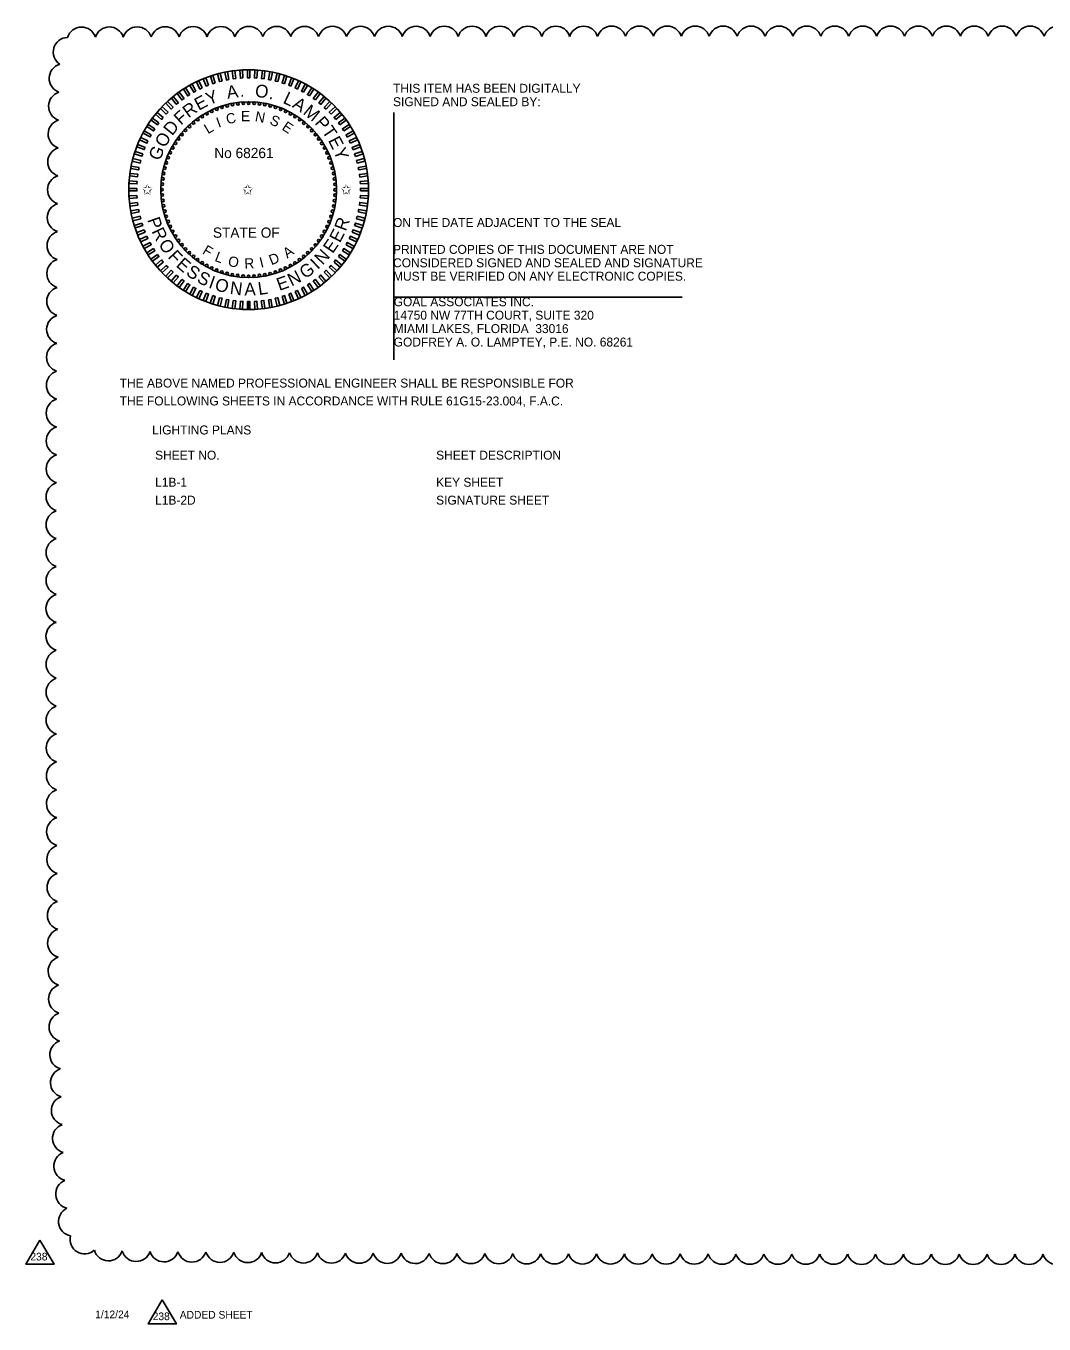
# Model space of a CAD drawing. Extents: x -811.2 to -795, y -2295.2 to -2235.1.
# Drawn here: x -811.23 to -803.27, y -2294.97 to -2284.82 of the extents above; entities that cross this region are included whole.
import ezdxf

# ---------------------------------------------------------------- set-up
doc = ezdxf.new("R2010")
doc.units = 0
for name, color, linetype in [('AdhocPoint_dp', 7, 'Continuous'), ('Cloud_dp', 7, 'Continuous'), ('PlotBorder_dp', 7, 'Continuous'), ('TextMinor', 7, 'Continuous'), ('TextMisc', 7, 'Continuous'), ('TextShtNo', 7, 'Continuous')]:
    doc.layers.add(name, color=color, linetype=linetype)

msp = doc.modelspace()

# ---------------------------------------------------------------- linework, layer by layer
at = {"layer": 'AdhocPoint_dp'}
for p, q in [((-808.355, -2285.496), (-808.355, -2287.431)), ((-808.355, -2286.941), (-806.098, -2286.941))]:
    msp.add_line(p, q, dxfattribs=at)
at = {"layer": 'Cloud_dp'}
for points in [[(-811.125, -2294.318), (-811.233, -2294.506), (-811.012, -2294.506)], [(-810.168, -2294.785), (-810.276, -2294.973), (-810.055, -2294.973)]]:
    msp.add_lwpolyline(points, close=True, dxfattribs=at)
for centre, start, end in [((-810.798, -2284.941), 18.0566, 163.0566), ((-810.58, -2284.94), 17.7998, 162.7998), ((-810.362, -2284.939), 17.7187, 162.7187), ((-810.143, -2284.938), 17.6743, 162.6743), ((-809.925, -2284.937), 17.6451, 162.6451), ((-809.707, -2284.937), 17.624, 162.624), ((-809.488, -2284.936), 17.6079, 162.6079), ((-809.27, -2284.936), 17.5951, 162.5951), ((-809.052, -2284.936), 17.5845, 162.5845), ((-808.834, -2284.935), 17.5756, 162.5756), ((-808.615, -2284.935), 17.568, 162.568), ((-808.397, -2284.935), 17.5614, 162.5614), ((-808.179, -2284.935), 17.5556, 162.5556), ((-807.96, -2284.934), 17.5505, 162.5505), ((-807.742, -2284.934), 17.5459, 162.5459), ((-807.524, -2284.934), 17.5417, 162.5417), ((-807.305, -2284.934), 17.5379, 162.5379), ((-807.087, -2284.934), 17.5344, 162.5344), ((-806.869, -2284.934), 17.5313, 162.5313), ((-806.65, -2284.933), 17.5283, 162.5283), ((-806.432, -2284.933), 17.5256, 162.5256), ((-806.214, -2284.933), 17.5231, 162.5231), ((-805.995, -2284.933), 17.5207, 162.5207), ((-805.777, -2284.933), 17.5185, 162.5185), ((-805.559, -2284.933), 17.5164, 162.5164), ((-805.34, -2284.933), 17.5145, 162.5145), ((-805.122, -2284.933), 17.5126, 162.5126), ((-804.904, -2284.933), 17.5109, 162.5109), ((-804.685, -2284.933), 17.5092, 162.5092), ((-804.467, -2284.933), 17.5077, 162.5077), ((-804.249, -2284.933), 17.5062, 162.5062), ((-804.03, -2284.933), 17.5048, 162.5048), ((-803.812, -2284.933), 17.5034, 162.5034), ((-803.594, -2284.933), 17.5021, 162.5021), ((-803.375, -2284.933), 17.5009, 162.5009), ((-803.157, -2284.933), 17.5, 162.5), ((-810.905, -2285.022), 91.4771, 236.4771), ((-810.937, -2285.228), 105.908, 250.908), ((-810.942, -2285.446), 106.4168, 251.4168), ((-810.945, -2285.664), 106.6762, 251.6762), ((-810.948, -2285.882), 106.841, 251.841), ((-810.95, -2286.1), 106.9576, 251.9576), ((-810.952, -2286.318), 107.0457, 252.0457), ((-810.954, -2286.537), 107.1154, 252.1154), ((-810.955, -2286.755), 107.1722, 252.1722), ((-810.956, -2286.973), 107.2198, 252.2198), ((-810.957, -2287.192), 107.2603, 252.2603), ((-810.958, -2287.41), 107.2954, 252.2954), ((-810.959, -2287.628), 107.3262, 252.3262), ((-810.96, -2287.847), 107.3535, 252.3535), ((-810.96, -2288.065), 107.3779, 252.3779), ((-810.96, -2288.283), 107.3998, 252.3998), ((-810.961, -2288.501), 107.4198, 252.4198), ((-810.961, -2288.72), 107.438, 252.438), ((-810.961, -2288.938), 107.4547, 252.4547), ((-810.961, -2289.156), 107.4701, 252.4701), ((-810.962, -2289.375), 107.4843, 252.4843), ((-810.962, -2289.593), 107.499, 252.499), ((-810.961, -2289.811), 107.5356, 252.5356), ((-810.961, -2290.03), 107.5822, 252.5822), ((-810.961, -2290.248), 107.6325, 252.6325), ((-810.96, -2290.466), 107.6869, 252.6869), ((-810.959, -2290.685), 107.7461, 252.7461), ((-810.958, -2290.903), 107.8108, 252.8108), ((-810.957, -2291.121), 107.8818, 252.8818), ((-810.955, -2291.339), 107.9604, 252.9604), ((-810.954, -2291.558), 108.0479, 253.0479), ((-810.951, -2291.776), 108.1461, 253.1461), ((-810.949, -2291.994), 108.2576, 253.2576), ((-810.945, -2292.212), 108.3854, 253.3854), ((-810.942, -2292.431), 108.534, 253.534), ((-810.938, -2292.649), 108.7099, 253.7099), ((-810.932, -2292.867), 108.9225, 253.9225), ((-810.927, -2293.085), 109.1867, 254.1867), ((-810.92, -2293.303), 109.5275, 254.5275), ((-810.911, -2293.521), 109.9909, 254.9909), ((-810.9, -2293.738), 110.6749, 255.6749), ((-810.886, -2293.956), 111.8417, 256.8417), ((-810.864, -2294.171), 114.6718, 259.6718), ((-810.774, -2294.311), 166.2299, 311.2299), ((-810.588, -2294.365), 196.1072, 341.1072), ((-810.37, -2294.37), 196.5738, 341.5738), ((-810.152, -2294.373), 196.7877, 341.7877), ((-809.934, -2294.375), 196.9179, 341.9179), ((-809.715, -2294.377), 197.008, 342.008), ((-809.497, -2294.379), 197.075, 342.075), ((-809.279, -2294.381), 197.1274, 342.1274), ((-809.061, -2294.382), 197.1699, 342.1699), ((-808.842, -2294.383), 197.2052, 342.2052), ((-808.624, -2294.384), 197.2352, 342.2352), ((-808.406, -2294.385), 197.261, 342.261), ((-808.187, -2294.386), 197.2836, 342.2836), ((-807.969, -2294.387), 197.3036, 342.3036), ((-807.751, -2294.387), 197.3214, 342.3214), ((-807.532, -2294.388), 197.3374, 342.3374), ((-807.314, -2294.389), 197.3519, 342.3519), ((-807.096, -2294.389), 197.3651, 342.3651), ((-806.878, -2294.39), 197.3773, 342.3773), ((-806.659, -2294.39), 197.3884, 342.3884), ((-806.441, -2294.391), 197.3987, 342.3987), ((-806.223, -2294.391), 197.4083, 342.4083), ((-806.004, -2294.391), 197.4172, 342.4172), ((-805.786, -2294.392), 197.4256, 342.4256), ((-805.568, -2294.392), 197.4334, 342.4334), ((-805.349, -2294.392), 197.4407, 342.4407), ((-805.131, -2294.392), 197.4476, 342.4476), ((-804.913, -2294.392), 197.4542, 342.4542), ((-804.694, -2294.393), 197.4604, 342.4604), ((-804.476, -2294.393), 197.4662, 342.4662), ((-804.258, -2294.393), 197.4718, 342.4718), ((-804.039, -2294.393), 197.4771, 342.4771), ((-803.821, -2294.393), 197.4821, 342.4821), ((-803.603, -2294.393), 197.487, 342.487), ((-803.384, -2294.393), 197.4916, 342.4916), ((-803.166, -2294.393), 197.496, 342.496)]:
    msp.add_arc(centre, 0.114, start, end, dxfattribs=at)
at = {"layer": 'TextMinor'}
for radius in [0.938, 0.688]:
    msp.add_circle((-809.49, -2286.099), radius, dxfattribs=at)
at = {"layer": 'TextShtNo'}
for p, q in [((-809.5, -2287.037), (-809.5, -2286.974)), ((-809.49, -2287.037), (-809.49, -2286.974)), ((-809.48, -2287.037), (-809.48, -2286.974))]:
    msp.add_line(p, q, dxfattribs=at)
for points in [[(-809.698, -2285.249), (-809.717, -2285.254), (-809.733, -2285.194), (-809.713, -2285.189)], [(-809.644, -2285.238), (-809.664, -2285.242), (-809.676, -2285.18), (-809.656, -2285.176)], [(-809.59, -2285.23), (-809.61, -2285.232), (-809.618, -2285.17), (-809.598, -2285.168)], [(-809.535, -2285.225), (-809.555, -2285.227), (-809.559, -2285.164), (-809.539, -2285.163)], [(-809.48, -2285.224), (-809.5, -2285.224), (-809.5, -2285.162), (-809.48, -2285.162)], [(-809.425, -2285.227), (-809.445, -2285.225), (-809.441, -2285.163), (-809.421, -2285.164)], [(-809.37, -2285.232), (-809.39, -2285.23), (-809.383, -2285.168), (-809.363, -2285.17)], [(-809.316, -2285.242), (-809.336, -2285.238), (-809.324, -2285.177), (-809.304, -2285.18)], [(-809.263, -2285.254), (-809.282, -2285.249), (-809.267, -2285.189), (-809.247, -2285.194)], [(-809.95, -2285.355), (-809.967, -2285.366), (-810.001, -2285.313), (-809.984, -2285.302)], [(-809.903, -2285.328), (-809.92, -2285.337), (-809.951, -2285.283), (-809.933, -2285.273)], [(-809.853, -2285.303), (-809.872, -2285.312), (-809.898, -2285.255), (-809.88, -2285.247)], [(-809.803, -2285.282), (-809.822, -2285.289), (-809.845, -2285.231), (-809.826, -2285.224)], [(-809.751, -2285.264), (-809.77, -2285.27), (-809.789, -2285.211), (-809.77, -2285.205)], [(-809.21, -2285.27), (-809.229, -2285.264), (-809.21, -2285.205), (-809.191, -2285.211)], [(-809.159, -2285.289), (-809.177, -2285.282), (-809.154, -2285.224), (-809.136, -2285.231)], [(-809.108, -2285.312), (-809.127, -2285.303), (-809.1, -2285.247), (-809.082, -2285.255)], [(-809.06, -2285.337), (-809.077, -2285.328), (-809.047, -2285.273), (-809.03, -2285.283)], [(-809.013, -2285.366), (-809.03, -2285.355), (-808.996, -2285.302), (-808.979, -2285.313)], [(-810.04, -2285.419), (-810.056, -2285.431), (-810.095, -2285.383), (-810.08, -2285.37)], [(-809.996, -2285.385), (-810.013, -2285.397), (-810.049, -2285.347), (-810.033, -2285.335)], [(-808.968, -2285.397), (-808.984, -2285.385), (-808.947, -2285.335), (-808.931, -2285.347)], [(-808.925, -2285.432), (-808.94, -2285.419), (-808.9, -2285.371), (-808.885, -2285.383)], [(-810.158, -2285.534), (-810.171, -2285.549), (-810.219, -2285.509), (-810.206, -2285.494)], [(-810.121, -2285.493), (-810.135, -2285.508), (-810.18, -2285.465), (-810.167, -2285.45)], [(-810.082, -2285.454), (-810.096, -2285.468), (-810.139, -2285.423), (-810.124, -2285.409)], [(-808.884, -2285.468), (-808.898, -2285.455), (-808.856, -2285.409), (-808.841, -2285.423)], [(-808.845, -2285.508), (-808.859, -2285.493), (-808.814, -2285.45), (-808.8, -2285.465)], [(-808.809, -2285.549), (-808.822, -2285.534), (-808.774, -2285.494), (-808.761, -2285.51)], [(-810.223, -2285.622), (-810.234, -2285.639), (-810.287, -2285.605), (-810.276, -2285.588)], [(-810.192, -2285.577), (-810.204, -2285.593), (-810.254, -2285.556), (-810.243, -2285.54)], [(-808.776, -2285.593), (-808.788, -2285.577), (-808.738, -2285.54), (-808.726, -2285.556)], [(-808.746, -2285.639), (-808.757, -2285.622), (-808.704, -2285.588), (-808.693, -2285.606)], [(-810.278, -2285.717), (-810.286, -2285.736), (-810.343, -2285.709), (-810.334, -2285.691)], [(-810.252, -2285.669), (-810.262, -2285.686), (-810.316, -2285.656), (-810.307, -2285.639)], [(-808.718, -2285.687), (-808.728, -2285.669), (-808.673, -2285.639), (-808.664, -2285.657)], [(-808.694, -2285.736), (-808.703, -2285.718), (-808.646, -2285.691), (-808.638, -2285.709)], [(-810.319, -2285.819), (-810.325, -2285.838), (-810.385, -2285.819), (-810.379, -2285.8)], [(-810.3, -2285.768), (-810.307, -2285.786), (-810.365, -2285.763), (-810.358, -2285.745)], [(-808.673, -2285.787), (-808.68, -2285.768), (-808.622, -2285.745), (-808.615, -2285.764)], [(-808.655, -2285.839), (-808.661, -2285.819), (-808.602, -2285.8), (-808.595, -2285.819)], [(-810.335, -2285.872), (-810.34, -2285.891), (-810.401, -2285.876), (-810.396, -2285.856)], [(-808.64, -2285.892), (-808.645, -2285.872), (-808.585, -2285.856), (-808.58, -2285.876)], [(-810.357, -2285.979), (-810.36, -2285.999), (-810.421, -2285.992), (-810.419, -2285.972)], [(-810.348, -2285.925), (-810.352, -2285.945), (-810.413, -2285.933), (-810.409, -2285.914)], [(-808.629, -2285.945), (-808.632, -2285.925), (-808.571, -2285.914), (-808.567, -2285.934)], [(-808.621, -2286), (-808.623, -2285.98), (-808.561, -2285.972), (-808.559, -2285.992)], [(-810.365, -2286.089), (-810.365, -2286.109), (-810.428, -2286.109), (-810.428, -2286.089)], [(-810.363, -2286.034), (-810.364, -2286.054), (-810.426, -2286.05), (-810.425, -2286.03)], [(-808.616, -2286.054), (-808.617, -2286.034), (-808.555, -2286.03), (-808.554, -2286.051)], [(-808.615, -2286.109), (-808.615, -2286.089), (-808.553, -2286.089), (-808.553, -2286.109)], [(-810.364, -2286.144), (-810.363, -2286.164), (-810.425, -2286.168), (-810.426, -2286.148)], [(-810.36, -2286.199), (-810.357, -2286.219), (-810.419, -2286.227), (-810.421, -2286.207)], [(-808.623, -2286.219), (-808.621, -2286.199), (-808.559, -2286.207), (-808.561, -2286.227)], [(-808.617, -2286.164), (-808.616, -2286.144), (-808.554, -2286.148), (-808.555, -2286.168)], [(-810.352, -2286.253), (-810.348, -2286.273), (-810.409, -2286.285), (-810.413, -2286.265)], [(-810.34, -2286.307), (-810.335, -2286.327), (-810.396, -2286.342), (-810.401, -2286.323)], [(-808.645, -2286.327), (-808.64, -2286.307), (-808.58, -2286.323), (-808.585, -2286.342)], [(-808.632, -2286.273), (-808.629, -2286.253), (-808.567, -2286.265), (-808.571, -2286.285)], [(-810.325, -2286.36), (-810.319, -2286.379), (-810.379, -2286.398), (-810.385, -2286.379)], [(-810.307, -2286.412), (-810.3, -2286.431), (-810.358, -2286.454), (-810.366, -2286.435)], [(-808.68, -2286.431), (-808.673, -2286.412), (-808.615, -2286.435), (-808.622, -2286.454)], [(-808.661, -2286.379), (-808.655, -2286.36), (-808.595, -2286.379), (-808.602, -2286.399)], [(-810.286, -2286.463), (-810.278, -2286.481), (-810.334, -2286.507), (-810.343, -2286.489)], [(-810.262, -2286.512), (-810.252, -2286.53), (-810.307, -2286.56), (-810.317, -2286.542)], [(-808.728, -2286.53), (-808.719, -2286.512), (-808.664, -2286.542), (-808.674, -2286.56)], [(-808.703, -2286.481), (-808.694, -2286.463), (-808.638, -2286.489), (-808.646, -2286.508)], [(-810.234, -2286.56), (-810.224, -2286.577), (-810.276, -2286.61), (-810.287, -2286.593)], [(-810.204, -2286.605), (-810.192, -2286.622), (-810.243, -2286.658), (-810.255, -2286.642)], [(-808.788, -2286.622), (-808.776, -2286.605), (-808.726, -2286.642), (-808.738, -2286.659)], [(-808.757, -2286.577), (-808.746, -2286.56), (-808.693, -2286.593), (-808.704, -2286.61)], [(-810.171, -2286.649), (-810.158, -2286.665), (-810.206, -2286.705), (-810.219, -2286.689)], [(-810.135, -2286.691), (-810.121, -2286.706), (-810.167, -2286.748), (-810.18, -2286.734)], [(-808.859, -2286.706), (-808.845, -2286.691), (-808.8, -2286.734), (-808.814, -2286.748)], [(-808.822, -2286.665), (-808.81, -2286.649), (-808.761, -2286.689), (-808.774, -2286.705)], [(-810.097, -2286.73), (-810.082, -2286.744), (-810.125, -2286.789), (-810.139, -2286.776)], [(-810.056, -2286.767), (-810.04, -2286.78), (-810.08, -2286.828), (-810.096, -2286.815)], [(-810.013, -2286.801), (-809.996, -2286.813), (-810.033, -2286.864), (-810.049, -2286.852)], [(-808.984, -2286.813), (-808.968, -2286.801), (-808.931, -2286.852), (-808.947, -2286.864)], [(-808.94, -2286.78), (-808.925, -2286.767), (-808.885, -2286.815), (-808.9, -2286.828)], [(-808.899, -2286.744), (-808.884, -2286.73), (-808.841, -2286.776), (-808.856, -2286.79)], [(-809.968, -2286.833), (-809.951, -2286.843), (-809.984, -2286.896), (-810.001, -2286.885)], [(-809.921, -2286.861), (-809.903, -2286.871), (-809.933, -2286.926), (-809.951, -2286.916)], [(-809.872, -2286.887), (-809.854, -2286.895), (-809.88, -2286.952), (-809.898, -2286.943)], [(-809.822, -2286.909), (-809.803, -2286.917), (-809.826, -2286.975), (-809.845, -2286.967)], [(-809.77, -2286.928), (-809.751, -2286.935), (-809.77, -2286.994), (-809.79, -2286.988)], [(-809.229, -2286.935), (-809.21, -2286.928), (-809.191, -2286.988), (-809.21, -2286.994)], [(-809.177, -2286.917), (-809.159, -2286.909), (-809.136, -2286.967), (-809.154, -2286.975)], [(-809.127, -2286.895), (-809.109, -2286.887), (-809.082, -2286.943), (-809.1, -2286.952)], [(-809.077, -2286.871), (-809.06, -2286.861), (-809.03, -2286.916), (-809.047, -2286.926)], [(-809.03, -2286.844), (-809.013, -2286.833), (-808.979, -2286.885), (-808.996, -2286.896)], [(-809.718, -2286.944), (-809.698, -2286.949), (-809.714, -2287.01), (-809.733, -2287.005)], [(-809.664, -2286.957), (-809.644, -2286.961), (-809.656, -2287.022), (-809.676, -2287.018)], [(-809.61, -2286.966), (-809.59, -2286.969), (-809.598, -2287.031), (-809.618, -2287.028)], [(-809.555, -2286.972), (-809.535, -2286.973), (-809.539, -2287.035), (-809.559, -2287.034)], [(-809.5, -2286.974), (-809.48, -2286.974), (-809.48, -2287.037), (-809.5, -2287.037)], [(-809.445, -2286.973), (-809.425, -2286.972), (-809.421, -2287.034), (-809.441, -2287.036)], [(-809.391, -2286.969), (-809.371, -2286.966), (-809.363, -2287.028), (-809.383, -2287.031)], [(-809.336, -2286.961), (-809.316, -2286.957), (-809.305, -2287.018), (-809.324, -2287.022)], [(-809.282, -2286.949), (-809.263, -2286.944), (-809.247, -2287.005), (-809.267, -2287.01)]]:
    msp.add_lwpolyline(points, close=True, dxfattribs=at)
for centre in [(-809.816, -2285.505), (-809.778, -2285.486), (-809.739, -2285.469), (-809.699, -2285.455), (-809.658, -2285.443), (-809.617, -2285.434), (-809.574, -2285.427), (-809.532, -2285.423), (-809.49, -2285.422), (-809.447, -2285.423), (-809.405, -2285.427), (-809.363, -2285.434), (-809.321, -2285.443), (-809.28, -2285.455), (-809.24, -2285.47), (-809.201, -2285.486), (-809.163, -2285.506), (-809.953, -2285.605), (-809.922, -2285.577), (-809.888, -2285.551), (-809.853, -2285.527), (-809.127, -2285.528), (-809.091, -2285.551), (-809.058, -2285.578), (-809.026, -2285.606), (-810.038, -2285.701), (-810.012, -2285.667), (-809.984, -2285.635), (-808.996, -2285.636), (-808.968, -2285.668), (-808.942, -2285.701), (-810.103, -2285.81), (-810.084, -2285.772), (-810.062, -2285.736), (-808.918, -2285.737), (-808.896, -2285.773), (-808.877, -2285.811), (-810.134, -2285.889), (-810.12, -2285.849), (-808.86, -2285.85), (-808.846, -2285.89), (-810.162, -2286.014), (-810.155, -2285.972), (-810.146, -2285.93), (-808.834, -2285.931), (-808.825, -2285.973), (-808.818, -2286.015), (-810.168, -2286.099), (-810.166, -2286.056), (-808.814, -2286.057), (-808.813, -2286.1), (-810.166, -2286.141), (-810.162, -2286.184), (-810.156, -2286.226), (-808.825, -2286.227), (-808.818, -2286.185), (-808.814, -2286.142), (-810.146, -2286.267), (-810.135, -2286.308), (-808.846, -2286.309), (-808.834, -2286.268), (-810.12, -2286.348), (-810.103, -2286.387), (-810.084, -2286.425), (-808.897, -2286.426), (-808.877, -2286.388), (-808.86, -2286.349), (-810.062, -2286.462), (-810.039, -2286.497), (-810.012, -2286.531), (-808.968, -2286.532), (-808.942, -2286.498), (-808.918, -2286.463), (-809.984, -2286.563), (-809.954, -2286.593), (-809.922, -2286.621), (-809.059, -2286.622), (-809.027, -2286.593), (-808.997, -2286.563), (-809.889, -2286.647), (-809.854, -2286.671), (-809.817, -2286.693), (-809.779, -2286.712), (-809.74, -2286.729), (-809.241, -2286.729), (-809.202, -2286.712), (-809.164, -2286.693), (-809.128, -2286.672), (-809.092, -2286.648), (-809.7, -2286.743), (-809.659, -2286.755), (-809.618, -2286.765), (-809.576, -2286.771), (-809.533, -2286.775), (-809.49, -2286.777), (-809.448, -2286.775), (-809.406, -2286.771), (-809.364, -2286.765), (-809.322, -2286.756), (-809.281, -2286.744)]:
    msp.add_circle(centre, 0.01, dxfattribs=at)

# ---------------------------------------------------------------- texts
at = {"layer": 'Cloud_dp'}
for p in [(-811.198, -2294.476), (-810.241, -2294.943)]:
    msp.add_text('238', height=0.06, rotation=0, dxfattribs=at).set_placement(p)
at = {"layer": 'PlotBorder_dp'}
for s, p in [('THIS ITEM HAS BEEN DIGITALLY', (-808.36, -2285.341)), ('SIGNED AND SEALED BY:', (-808.36, -2285.446)), ('ON THE DATE ADJACENT TO THE SEAL', (-808.36, -2286.391)), ('PRINTED COPIES OF THIS DOCUMENT ARE NOT ', (-808.36, -2286.601)), ('CONSIDERED SIGNED AND SEALED AND SIGNATURE ', (-808.36, -2286.706)), ('MUST BE VERIFIED ON ANY ELECTRONIC COPIES.', (-808.36, -2286.811)), ('GOAL ASSOCIATES INC.', (-808.355, -2287.011)), ('14750 NW 77TH COURT, SUITE 320', (-808.355, -2287.116)), ('MIAMI LAKES, FLORIDA  33016', (-808.355, -2287.221)), ('GODFREY A. O. LAMPTEY, P.E. NO. 68261', (-808.355, -2287.326)), ('THE ABOVE NAMED PROFESSIONAL ENGINEER SHALL BE RESPONSIBLE FOR ', (-810.499, -2287.647)), ('THE FOLLOWING SHEETS IN ACCORDANCE WITH RULE 61G15-23.004, F.A.C.', (-810.499, -2287.787)), ('LIGHTING PLANS', (-810.245, -2288.014))]:
    msp.add_text(s, height=0.07, dxfattribs=at).set_placement(p)
at = {"layer": 'TextMinor'}
for s, p in [('1/12/24', (-810.691, -2294.928)), ('ADDED SHEET', (-810.029, -2294.931))]:
    msp.add_text(s, height=0.06, dxfattribs=at).set_placement(p)
at = {"layer": 'TextMisc'}
for s, p in [('SHEET NO.', (-810.222, -2288.211)), ('SHEET DESCRIPTION', (-808.023, -2288.211)), ('L1B-1', (-810.222, -2288.423)), ('KEY SHEET', (-808.023, -2288.423)), ('L1B-2D', (-810.222, -2288.563)), ('SIGNATURE SHEET', (-808.023, -2288.563))]:
    msp.add_text(s, height=0.07, dxfattribs=at).set_placement(p)
at = {"layer": 'TextShtNo'}
for s, height, rotation, p in [('A', 0.1, 8.8088, (-809.655, -2285.389)), ('O', 0.1, 352.1877, (-809.445, -2285.371)), ('E', 0.1, 28.1055, (-809.881, -2285.483)), ('Y', 0.1, 21.0633, (-809.802, -2285.44)), ('.', 0.1, 1.0418, (-809.558, -2285.373)), ('.', 0.1, 343.5268, (-809.336, -2285.386)), ('L', 0.1, 334.6727, (-809.228, -2285.418)), ('A', 0.1, 328.4096, (-809.155, -2285.451)), ('F', 0.1, 42.3772, (-810.02, -2285.598)), ('R', 0.1, 35.9269, (-809.961, -2285.542)), ('C', 0.08, 12.2025, (-809.658, -2285.588)), ('E', 0.08, 0.4186, (-809.55, -2285.564)), ('N', 0.08, 349.2914, (-809.445, -2285.563)), ('M', 0.1, 320.6426, (-809.071, -2285.502)), ('D', 0.1, 50.8569, (-810.089, -2285.682)), ('L', 0.08, 30.4021, (-809.809, -2285.666)), ('I', 0.08, 20.0117, (-809.726, -2285.615)), ('S', 0.08, 337.0221, (-809.332, -2285.584)), ('E', 0.08, 325.8663, (-809.236, -2285.625)), ('P', 0.1, 311.1966, (-808.978, -2285.579)), ('T', 0.1, 304.4563, (-808.921, -2285.643)), ('O', 0.1, 59.5178, (-810.145, -2285.777)), ('E', 0.1, 297.6315, (-808.871, -2285.714)), ('G', 0.1, 68.0518, (-810.185, -2285.878)), ('Y', 0.1, 290.5893, (-808.828, -2285.793)), ('P', 0.1, 289.4055, (-810.285, -2286.334)), ('R', 0.1, 69.5134, (-808.73, -2286.429)), ('R', 0.1, 296.1458, (-810.252, -2286.425)), ('E', 0.1, 62.4712, (-808.776, -2286.52)), ('O', 0.1, 303.9671, (-810.2, -2286.526)), ('E', 0.1, 55.4289, (-808.833, -2286.604)), ('F', 0.1, 312.628, (-810.128, -2286.628)), ('F', 0.08, 328.7241, (-809.858, -2286.596)), ('L', 0.08, 339.2916, (-809.761, -2286.655)), ('O', 0.08, 349.6821, (-809.656, -2286.695)), ('D', 0.08, 22.0128, (-809.312, -2286.691)), ('A', 0.08, 34.4992, (-809.188, -2286.639)), ('N', 0.1, 47.1788, (-808.912, -2286.693)), ('E', 0.1, 319.0783, (-810.064, -2286.696)), ('S', 0.1, 326.1206, (-809.987, -2286.762)), ('R', 0.08, 2.3398, (-809.522, -2286.717)), ('I', 0.08, 14.2037, (-809.394, -2286.71)), ('G', 0.1, 35.1115, (-809.049, -2286.801)), ('I', 0.1, 43.6456, (-808.95, -2286.728)), ('S', 0.1, 333.193, (-809.902, -2286.819)), ('I', 0.1, 340.2654, (-809.81, -2286.864)), ('O', 0.1, 343.7986, (-809.762, -2286.882)), ('N', 0.1, 352.4595, (-809.641, -2286.914)), ('A', 0.1, 0.7097, (-809.523, -2286.927)), ('L', 0.1, 8.4767, (-809.41, -2286.924)), ('E', 0.1, 19.8191, (-809.25, -2286.892)), ('N', 0.1, 26.8614, (-809.154, -2286.857))]:
    msp.add_text(s, height=height, rotation=rotation, dxfattribs=at).set_placement(p)
for s, p in [('No 68261', (-809.759, -2285.852)), ('✩', (-810.325, -2286.137)), ('✩', (-809.54, -2286.137)), ('✩', (-808.769, -2286.137)), ('STATE OF', (-809.77, -2286.475))]:
    msp.add_text(s, height=0.08, dxfattribs=at).set_placement(p)

doc.saveas('drawing.dxf')
